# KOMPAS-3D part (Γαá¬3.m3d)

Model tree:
1. Эскиз:1
2. Операция выдавливания:1
     Расстояние 1 = 11.9; Расстояние 2 = 1
3. Скругление:22
     Радиус = 5
4. Скругление:23
     Радиус = 5
5. Эскиз:7
6. Операция выдавливания:4
     Расстояние 1 = 1.8
7. Эскиз:8
8. Вырезать элемент выдавливания:4
     Расстояние 2 = 0.2; Расстояние 1 = 0.2
9. Фаска:1
     Угол = 45; Длина 1 = 0.5; Длина 2 = 0.5
10. Фаска:2
     Угол = 45; Длина 1 = 0.5; Длина 2 = 0.5
11. Скругление:26
     Радиус = 0.5
12. Скругление:27
     Радиус = 0.5
13. Скругление:28
     Радиус = 0.1
14. Скругление:29
     Радиус = 0.1
15. Скругление:30
     Радиус = 0.1
16. Скругление:32
     Радиус = 0.1
17. Скругление:33
     Радиус = 0.1
18. Скругление:34
     Радиус = 0.1
19. Скругление:40
     Радиус = 0.1
20. Эскиз:9
21. Операция выдавливания:5
     Расстояние 1 = 1.8; Расстояние 2 = 2.5
22. Скругление:41
     Радиус = 0.2
23. Скругление:42
     Радиус = 0.2
24. Скругление:43
     Радиус = 0.5
25. Скругление:44
     Радиус = 0.5
26. Скругление:45
     Радиус = 0.2
27. Эскиз:11
28. Эскиз:12
29. Операция выдавливания:6
     Расстояние 1 = 11.9; Расстояние 2 = 1.5
30. Скругление:47
     Радиус = 0.1
31. Скругление:48
     Радиус = 0.1
32. Эскиз:13
33. Операция выдавливания:7
     Расстояние 1 = 11.9; Расстояние 2 = 2
34. Скругление:49
     Радиус = 2
35. Скругление:50
     Радиус = 2
36. Скругление:51
     Радиус = 0.2
37. Скругление:52
     Радиус = 0.1
38. Скругление:53
     Радиус = 0.1
39. Скругление:54
     Радиус = 0.1
40. Скругление:55
     Радиус = 0.1
41. Скругление:56
     Радиус = 0.1
42. Вырезать элемент выдавливания:6
     Расстояние 1 = 11.9
43. Скругление:57
     Радиус = 0.1

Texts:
  трак3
